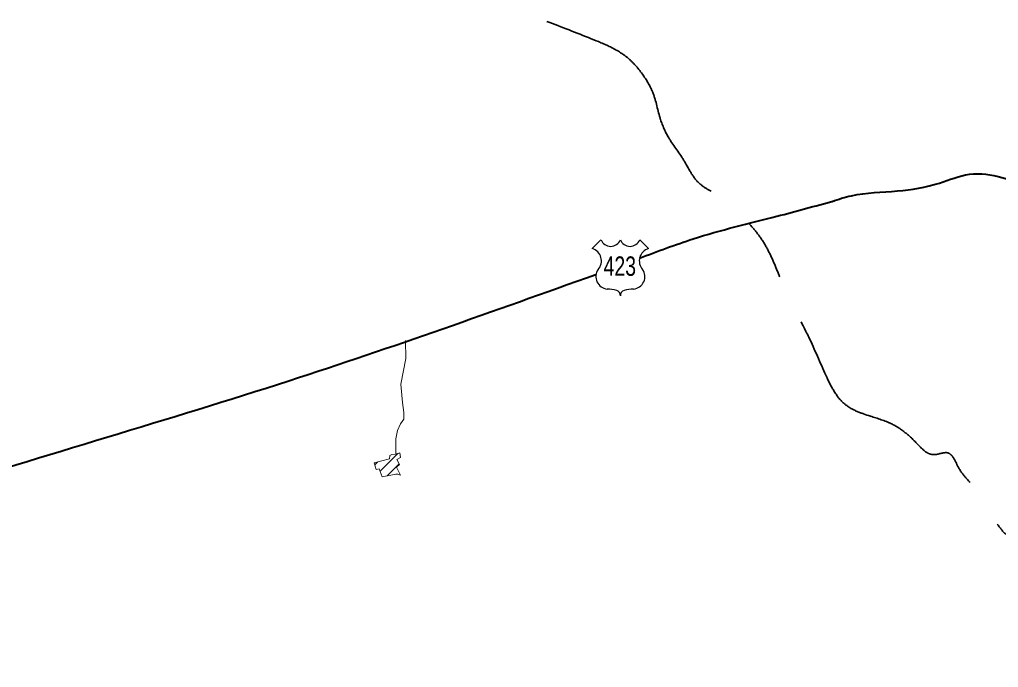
# Model space of a CAD drawing. Extents: x 553962 to 842807, y 8883888 to 9032388.
# Drawn here: x 598478 to 602011, y 8916653 to 8918990 of the extents above; entities that cross this region are included whole.
import ezdxf
from ezdxf.enums import TextEntityAlignment as Align

# ---------------------------------------------------------------- set-up
doc = ezdxf.new("R2010")
doc.units = 0
doc.header["$LTSCALE"] = 150
doc.linetypes.add('LONG_DASH_SHORT_DASH', pattern=[9.9, 6, -1.2, 1.5, -1.2])
doc.layers.add('6', color=7, linetype='Continuous', lineweight=13)

msp = doc.modelspace()

# ---------------------------------------------------------------- linework, layer by layer
at = {"layer": '6', "lineweight": 25}
for p, q in [((600544.7, 8918164.1), (600576.6, 8918196.1)), ((600716.5, 8918196.1), (600748.5, 8918164.1))]:
    msp.add_line(p, q, dxfattribs=at)
at = {"layer": '6'}
for p, q in [((599779.1, 8917360.8), (599843, 8917424.7)), ((599760.1, 8917384.1), (599770.4, 8917394.5)), ((599804.6, 8917343.8), (599848.1, 8917387.3)), ((599850.7, 8917347.5), (599851.7, 8917348.5))]:
    msp.add_line(p, q, dxfattribs=at)
msp.add_lwpolyline([(599871, 8917832.6), (599871.8, 8917767.7), (599854.5, 8917674.6), (599859.5, 8917608.7), (599864.6, 8917573), (599864.4, 8917548.3), (599853.3, 8917532), (599842.1, 8917507.4), (599836.4, 8917477.3), (599835.9, 8917422.3)], dxfattribs=at)
msp.add_lwpolyline([(599850.5, 8917427.2), (599834.3, 8917421.8), (599821.6, 8917421.3), (599813.8, 8917417.5), (599813.2, 8917405.3), (599758.2, 8917391.4), (599764.6, 8917366.4), (599775.7, 8917369.7), (599787.1, 8917340.2), (599836, 8917350.3), (599843.2, 8917350.2), (599852.5, 8917346.8), (599837.8, 8917375.8), (599849.5, 8917384.5), (599839.7, 8917403.4), (599853.1, 8917410)], close=True, dxfattribs=at)
at = {"layer": '6', "lineweight": 25}
for centre, radius, start, end in [((600611.6, 8918209.5), 37.4, 200.9593, 339.0407), ((600681.5, 8918209.5), 37.4, 200.9593, 339.0407), ((600532.2, 8918119.7), 46.1, 317.5721, 74.3689), ((600760.9, 8918119.7), 46.1, 105.6277, 222.4279), ((600602.9, 8918062.7), 44.9, 144.7373, 264.6578), ((600690.2, 8918062.7), 44.9, 275.3422, 35.2627), ((600598.5, 8917900), 118, 72.8937, 89.9006), ((600627.7, 8917994.7), 18.9, 357.6934, 72.9296), ((600665.4, 8917994.7), 18.9, 107.0704, 182.3065), ((600694.6, 8917900), 118, 90.0994, 107.1063)]:
    msp.add_arc(centre, radius, start, end, dxfattribs=at)
at = {"layer": '6'}
for points in [[(598300.5, 8917392.3), (598315.3, 8917441.1), (598255.3, 8917504.1), (598239.6, 8917592.4), (598271.1, 8917724.9), (598331, 8917860.5), (598362.6, 8917945.7), (598337.3, 8918008.8), (598271.1, 8918059.2), (598264.8, 8918122.3), (598283.7, 8918169.6), (598293.2, 8918216.9), (598258.5, 8918251.6), (598220.6, 8918330.5), (598230.1, 8918494.5), (598230.1, 8918586), (598223.8, 8918652.2), (598198.6, 8918705.8), (598223.8, 8918775.2), (598277.4, 8918895.6), (598337.3, 8919006), (598365.7, 8919135.4), (598368.9, 8919223.8), (598359.4, 8919260.4), (598397.3, 8919298.2), (598463.5, 8919374), (598532.9, 8919493.9), (598564.4, 8919569.6), (598630.7, 8919607.5), (598678, 8919639.1), (598668.5, 8919676.9), (598715.8, 8919736.9), (598775.8, 8919809.5), (598854.6, 8919853.7), (598920.8, 8919907.3)], [(601609.2, 8914720.1), (601610.4, 8914757.2), (601607.5, 8914794.4), (601595.3, 8914840.8), (601588.3, 8914877.4), (601584.2, 8914897.8), (601587.2, 8914923.4), (601583.7, 8914959.4), (601575.5, 8914976.8), (601580.2, 8914990.7), (601580.2, 8915008.2), (601585.4, 8915021.5), (601583.1, 8915041.8), (601574.4, 8915045.9), (601573.2, 8915055.8), (601581.3, 8915069.7), (601597.6, 8915091.2), (601625.5, 8915115), (601652.7, 8915131.2), (601691.6, 8915149.2), (601715.4, 8915173), (601725.8, 8915195.1), (601729.3, 8915251.6), (601734, 8915267.3), (601750.8, 8915290.5), (601770.5, 8915312), (601789.1, 8915326), (601829.1, 8915341.6), (601860.5, 8915353.8), (601900.5, 8915378.2), (601947.5, 8915399.7), (601991.6, 8915429.9), (602050.8, 8915463.6), (602115.8, 8915492.6), (602158.7, 8915505.4), (602314.3, 8915536.7), (602476.2, 8915677.8), (602669.4, 8915813.7), (602862.7, 8915954.7), (603014.1, 8916106.3), (603097.7, 8916148.1), (603186.5, 8916137.6), (603238.7, 8916163.8), (603270, 8916247.4), (603290.9, 8916378), (603348.4, 8916461.6), (603437.2, 8916492.9), (603499.8, 8916524.3), (603536.4, 8916555.7), (603567.7, 8916691.5), (603620, 8916775.1), (603620, 8916874.4), (603661.7, 8916952.8), (603729.6, 8917041.6), (603828.9, 8917146.1)]]:
    msp.add_spline(points, degree=3, dxfattribs=at)
at = {"layer": '6', "linetype": 'LONG_DASH_SHORT_DASH', "lineweight": 35}
msp.add_spline([(600381.6, 8918983.9), (600541.4, 8918921.3), (600673.5, 8918851.8), (600729.1, 8918789.3), (600763.8, 8918726.8), (600791.6, 8918629.5), (600819.4, 8918566.9), (600875, 8918483.6), (600930.6, 8918400.2), (601007, 8918351.5), (601076.5, 8918289), (601146, 8918212.6), (601243.3, 8918011), (601326.7, 8917844.3), (601389.2, 8917705.3), (601458.7, 8917601.1), (601549, 8917559.4), (601625.5, 8917531.6), (601715.8, 8917462.1), (601778.3, 8917420.4), (601827, 8917427.3), (601868.7, 8917371.8), (601924.2, 8917302.3), (602042.4, 8917128.5), (602132.7, 8917059.1), (602195.3, 8916968.7), (602237, 8916871.4), (602293.6, 8916815.3), (602362.3, 8916791.5), (602370.9, 8916763.8), (602382.4, 8916729.4), (602386.2, 8916632), (602375.9, 8916614.3), (602341.3, 8916526), (602362, 8916503.2), (602415.8, 8916437.2), (602443.5, 8916415.3), (602473.2, 8916343.3), (602487.1, 8916183.5), (602501, 8916086.2), (602528.4, 8916025.6), (602570.4, 8915982.6), (602548.4, 8915898.7), (602535.1, 8915867.2), (602486.4, 8915817.5), (602441.6, 8915736.4), (602464.5, 8915679.2), (602557, 8915738.3), (602710.7, 8915862.4), (602741.2, 8915892.9), (602862.4, 8915972.1), (603008.4, 8916103.8), (603086.7, 8916151.5), (603209.8, 8916155.7), (603293.2, 8916155.7)], degree=3, dxfattribs=at)
at = {"layer": '6', "lineweight": 40}
for points in [[(601410.6, 8918334.5), (601480.5, 8918354.8), (601646.5, 8918371.9), (601798.2, 8918400.6), (601906.9, 8918432.1), (602024.2, 8918420.6), (602124.4, 8918386.2), (602247.5, 8918383.4), (602364.8, 8918414.9), (602473.5, 8918412), (602596.6, 8918403.4), (602713.9, 8918400.6), (602825.5, 8918446.4), (602962.9, 8918515.1), (603180.4, 8918558), (603380.7, 8918598.1), (603598.2, 8918666.8), (603804.2, 8918755.6), (603978.8, 8918830), (604145.9, 8918875.8), (604200.3, 8918893), (604251.8, 8918870.1), (604446.4, 8918801.4), (604606.7, 8918732.7), (604769.8, 8918601)], [(600716.1, 8918129.4), (600909.4, 8918199.2), (601211.8, 8918280.7), (601418.4, 8918336.7)], [(596244.3, 8916699.1), (596768.6, 8916837.7), (598135.3, 8917279.9), (599449.7, 8917687.2), (600558.2, 8918071.1)]]:
    msp.add_spline(points, degree=3, dxfattribs=at)

# ---------------------------------------------------------------- texts
at = {"layer": '6', "width": 0.75}
msp.add_text('423', height=70, dxfattribs=at).set_placement((600644.5, 8918065.8), align=Align.CENTER)

doc.saveas('drawing.dxf')
